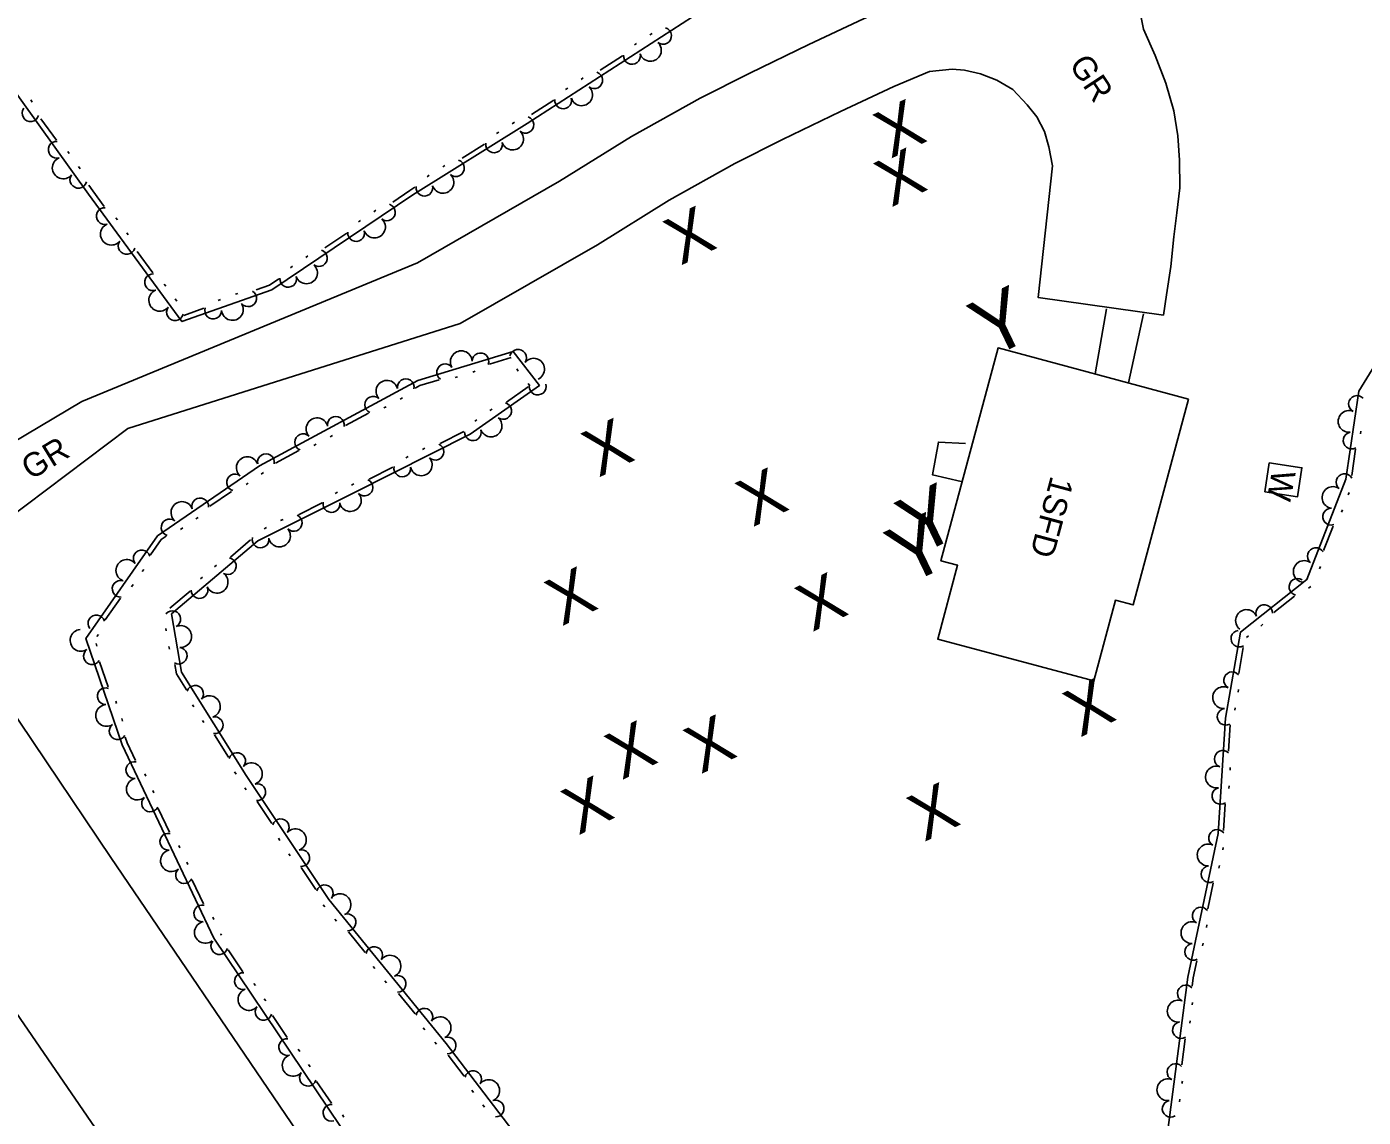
# Model space of a CAD drawing. Extents: x 2030130 to 2036320, y 723205 to 762423.
# Drawn here: x 2033389.9 to 2033597.2, y 761198.4 to 761367.6 of the extents above; entities that cross this region are included whole.
import ezdxf

# ---------------------------------------------------------------- set-up
doc = ezdxf.new("R2010")
doc.units = 0
for name, color, linetype in [('Draft_Station Labels Major', 7, 'Continuous'), ('Draft_Station Tics Major', 7, 'Continuous'), ('Exist Terrain Model Ground Surface', 7, 'Continuous'), ('Old_Level_23', 7, 'Continuous'), ('Old_Level_28', 7, 'Continuous')]:
    doc.layers.add(name, color=color, linetype=linetype)

msp = doc.modelspace()

# ---------------------------------------------------------------- linework, layer by layer
at = {"layer": 'Draft_Station Labels Major'}
for p, q in [((2033450.49, 761331), (2033398.43, 761309.47)), ((2033457.11, 761321.56), (2033405.58, 761305.29))]:
    msp.add_line(p, q, dxfattribs=at)
for points in [[(2033450.49, 761331), (2033472.55, 761343.63), (2033483.7, 761350.58), (2033494.36, 761356.54), (2033502.08, 761360.39), (2033511.2, 761364.83), (2033519.73, 761368.8), (2033525.39, 761371.23)], [(2033562.32, 761371.35), (2033563.15, 761367.2), (2033564.95, 761363.15), (2033566.59, 761358.86), (2033567.83, 761354.54), (2033568.47, 761350.65), (2033568.74, 761346.9), (2033568.77, 761342.61), (2033568.3, 761338.73), (2033567.84, 761335.02), (2033567.41, 761330.4), (2033566.71, 761326.01), (2033566.24, 761322.86), (2033546.8, 761325.6), (2033549.01, 761346.01), (2033548.45, 761348.99), (2033547.76, 761351.35), (2033546.62, 761353.61), (2033545.09, 761355.46), (2033542.86, 761357.87), (2033540.41, 761359.31), (2033537.84, 761360.29), (2033535.35, 761360.85), (2033533.46, 761361.02), (2033529.92, 761360.67)], [(2033457.11, 761321.56), (2033478.45, 761333.78), (2033489.54, 761340.69), (2033499.73, 761346.39), (2033507.16, 761350.09), (2033516.13, 761354.46), (2033524.42, 761358.32), (2033529.92, 761360.67)], [(2033712.22, 760786.66), (2033683.84, 760828.02), (2033655.87, 760868.99), (2033628.83, 760908.43), (2033600.16, 760950.82), (2033571.79, 760992.23), (2033543.75, 761033.03), (2033515.6, 761074.29), (2033487.47, 761115.18), (2033459.15, 761156.4), (2033430.9, 761197.59), (2033402.93, 761238.74), (2033380.71, 761271.71), (2033360.2, 761301.06), (2033346.96, 761320.77)], [(2033361.9, 761300.44), (2033372.02, 761296.58), (2033378.83, 761297.84), (2033398.43, 761309.47)], [(2033325.26, 761306.74), (2033353.27, 761265.49), (2033381.46, 761224.47), (2033409.65, 761183.47), (2033437.67, 761142.45), (2033465.74, 761101.32), (2033493.99, 761060.24), (2033522.13, 761019.11), (2033550.25, 760977.98), (2033578.36, 760936.85), (2033606.28, 760895.5), (2033634.33, 760854.29), (2033662.48, 760813.18), (2033690.27, 760771.87)], [(2033405.58, 761305.29), (2033386.64, 761290.99), (2033380.05, 761284.03), (2033381.74, 761273.53)]]:
    msp.add_lwpolyline(points, dxfattribs=at)
at = {"layer": 'Draft_Station Tics Major'}
for points in [[(2033496.38, 761371.21), (2033467.55, 761352.57), (2033449.79, 761341.52), (2033427.9, 761326.78), (2033413.97, 761321.85), (2033399.47, 761341.65), (2033376.06, 761374.31)], [(2033484.5, 761365), (2033484.16, 761364.78)], [(2033486.91, 761366.56), (2033486.57, 761366.33)], [(2033482.32, 761363.09), (2033478.87, 761360.87)], [(2033476.24, 761359.65), (2033475.89, 761359.43)], [(2033473.83, 761358.09), (2033473.48, 761357.87)], [(2033390.76, 761355.91), (2033390.52, 761356.24)], [(2033471.64, 761356.19), (2033468.2, 761353.96)], [(2033394.49, 761350), (2033392.1, 761353.33)], [(2033465.57, 761352.78), (2033465.22, 761352.56)], [(2033463.13, 761351.26), (2033462.78, 761351.05)], [(2033396.5, 761347.91), (2033396.26, 761348.24)], [(2033460.91, 761349.4), (2033457.43, 761347.23)], [(2033398.17, 761345.57), (2033397.93, 761345.91)], [(2033452.34, 761344.55), (2033451.99, 761344.33)], [(2033454.77, 761346.07), (2033454.42, 761345.85)], [(2033401.92, 761339.69), (2033400.14, 761342.13), (2033399.51, 761343)], [(2033450.11, 761342.69), (2033449.34, 761342.2), (2033446.67, 761340.41)], [(2033403.95, 761337.62), (2033403.7, 761337.95)], [(2033444.06, 761339.14), (2033443.72, 761338.91)], [(2033441.68, 761337.54), (2033441.34, 761337.31)], [(2033405.64, 761335.3), (2033405.4, 761335.63)], [(2033439.53, 761335.59), (2033436.12, 761333.3)], [(2033409.43, 761329.44), (2033407.01, 761332.75)], [(2033433.52, 761332.04), (2033433.17, 761331.81)], [(2033431.13, 761330.44), (2033430.79, 761330.21)], [(2033411.46, 761327.36), (2033411.22, 761327.69)], [(2033428.98, 761328.49), (2033427.53, 761327.52), (2033425.51, 761326.8)], [(2033413.16, 761325.05), (2033412.92, 761325.38)], [(2033422.66, 761326.23), (2033422.28, 761326.1)], [(2033417.39, 761323.93), (2033414.27, 761322.83)], [(2033419.96, 761325.28), (2033419.57, 761325.14)], [(2033604, 761323.17), (2033596.57, 761311.06), (2033594.52, 761297.4), (2033588.46, 761281.83), (2033578.2, 761273.7), (2033575.86, 761260.34), (2033574.71, 761242.44), (2033570.04, 761220.18), (2033566.67, 761194.48)], [(2033485.97, 761169.22), (2033454.96, 761209.86), (2033436.75, 761232.24), (2033423.94, 761251.45), (2033413.9, 761267.5), (2033412.33, 761276.52), (2033425.74, 761287.86), (2033440.52, 761295.23), (2033458.67, 761304.38), (2033469.44, 761311.97), (2033465.34, 761317.24), (2033450.59, 761312.7), (2033426, 761299.51), (2033410.19, 761288.65), (2033399.08, 761272.7), (2033404.72, 761256.21), (2033418.93, 761226.23), (2033495.84, 761111.88)], [(2033465.04, 761316.29), (2033461.7, 761315.27)], [(2033456.73, 761313.31), (2033456.34, 761313.18)], [(2033459.47, 761314.15), (2033459.08, 761314.03)], [(2033466.15, 761314.19), (2033465.9, 761314.51)], [(2033453.86, 761312.85), (2033450.9, 761311.94), (2033450.16, 761311.54)], [(2033464.33, 761309.38), (2033467.68, 761311.74)], [(2033467.92, 761311.92), (2033467.67, 761312.25)], [(2033448.18, 761310.02), (2033447.82, 761309.82)], [(2033442.93, 761307.66), (2033439.32, 761305.72)], [(2033445.66, 761308.66), (2033445.29, 761308.46)], [(2033461.75, 761308.06), (2033462.08, 761308.29)], [(2033454.02, 761302.95), (2033457.68, 761304.8)], [(2033459.4, 761306.4), (2033459.74, 761306.64)], [(2033596.88, 761304.85), (2033596.82, 761304.44)], [(2033434.81, 761302.84), (2033434.45, 761302.65)], [(2033437.34, 761304.2), (2033436.98, 761304)], [(2033432.09, 761301.84), (2033428.48, 761299.9)], [(2033448.71, 761300.73), (2033449.07, 761300.92)], [(2033451.27, 761302.03), (2033451.64, 761302.21)], [(2033596.05, 761302.07), (2033595.44, 761298.01)], [(2033426.62, 761298.44), (2033426.28, 761298.21)], [(2033443.03, 761297.41), (2033446.69, 761299.26)], [(2033424.26, 761296.82), (2033423.92, 761296.58)], [(2033440.28, 761296.49), (2033440.65, 761296.67)], [(2033421.66, 761295.53), (2033418.28, 761293.21)], [(2033437.72, 761295.21), (2033438.09, 761295.39)], [(2033595.04, 761295.35), (2033594.9, 761294.97)], [(2033432.03, 761291.91), (2033435.7, 761293.74)], [(2033594, 761292.68), (2033593.85, 761292.3)], [(2033416.48, 761291.48), (2033416.14, 761291.24)], [(2033429.28, 761290.99), (2033429.65, 761291.18)], [(2033592.58, 761290.15), (2033591.09, 761286.33)], [(2033411.51, 761288.57), (2033410.77, 761288.06), (2033409.11, 761285.67)], [(2033414.11, 761289.85), (2033413.77, 761289.62)], [(2033426.71, 761289.71), (2033427.08, 761289.9)], [(2033421.5, 761285.34), (2033424.63, 761287.99)], [(2033419.04, 761283.8), (2033419.35, 761284.07)], [(2033590.58, 761283.89), (2033590.43, 761283.5)], [(2033408.04, 761283.42), (2033407.81, 761283.08)], [(2033416.85, 761281.95), (2033417.16, 761282.22)], [(2033406.41, 761281.07), (2033406.17, 761280.73)], [(2033412.1, 761277.4), (2033415.23, 761280.05)], [(2033589.08, 761280.75), (2033588.76, 761280.5)], [(2033404.43, 761278.94), (2033402.08, 761275.58)], [(2033586.57, 761279.29), (2033583.36, 761276.75)], [(2033411.54, 761273.87), (2033411.47, 761274.27)], [(2033581.68, 761274.9), (2033581.36, 761274.64)], [(2033400.66, 761271.91), (2033400.79, 761271.52)], [(2033401.01, 761273.32), (2033400.78, 761272.99)], [(2033412.03, 761271.04), (2033411.96, 761271.45)], [(2033579.43, 761273.12), (2033579.11, 761272.86)], [(2033578.61, 761271.33), (2033577.91, 761267.29)], [(2033401.19, 761269.06), (2033402.52, 761265.18)], [(2033414.66, 761264.73), (2033413.12, 761267.2), (2033412.86, 761268.69)], [(2033577.89, 761264.8), (2033577.81, 761264.39)], [(2033403.7, 761262.99), (2033403.84, 761262.6)], [(2033415.84, 761262.08), (2033415.62, 761262.43)], [(2033577.39, 761261.97), (2033577.32, 761261.56)], [(2033404.63, 761260.27), (2033404.76, 761259.88)], [(2033417.36, 761259.65), (2033417.14, 761260)], [(2033576.61, 761259.29), (2033576.35, 761255.2)], [(2033405.17, 761257.42), (2033405.48, 761256.52), (2033406.79, 761253.76)], [(2033421.19, 761254.3), (2033419.01, 761257.78)], [(2033408.21, 761251.71), (2033408.39, 761251.34)], [(2033422.36, 761251.65), (2033422.14, 761252)], [(2033576.6, 761252.71), (2033576.58, 761252.3)], [(2033409.44, 761249.11), (2033409.62, 761248.74)], [(2033423.95, 761249.21), (2033423.72, 761249.55)], [(2033576.42, 761249.85), (2033576.39, 761249.44)], [(2033427.93, 761243.98), (2033425.65, 761247.4)], [(2033575.83, 761247.01), (2033575.57, 761242.92)], [(2033410.3, 761246.34), (2033412.06, 761242.64)], [(2033413.49, 761240.59), (2033413.66, 761240.22)], [(2033429.18, 761241.37), (2033428.96, 761241.71)], [(2033430.78, 761238.98), (2033430.55, 761239.32)], [(2033575.52, 761240.3), (2033575.44, 761239.9)], [(2033414.72, 761238), (2033414.89, 761237.63)], [(2033434.76, 761233.75), (2033432.48, 761237.16)], [(2033574.93, 761237.49), (2033574.85, 761237.09)], [(2033415.58, 761235.23), (2033417.33, 761231.52)], [(2033573.94, 761234.76), (2033573.1, 761230.75)], [(2033436.12, 761231.07), (2033435.86, 761231.39)], [(2033418.76, 761229.48), (2033418.93, 761229.1)], [(2033437.93, 761228.84), (2033437.67, 761229.16)], [(2033572.99, 761228.26), (2033572.91, 761227.85)], [(2033419.99, 761226.88), (2033420, 761226.85), (2033420.11, 761226.69)], [(2033442.39, 761224.01), (2033439.8, 761227.19)], [(2033421.14, 761224.42), (2033423.43, 761221.02)], [(2033572.4, 761225.45), (2033572.32, 761225.05)], [(2033443.88, 761221.53), (2033443.63, 761221.84)], [(2033571.41, 761222.72), (2033570.85, 761220.04), (2033570.68, 761218.75)], [(2033445.7, 761219.3), (2033445.44, 761219.62)], [(2033425.14, 761219.21), (2033425.37, 761218.86)], [(2033450.15, 761214.47), (2033447.57, 761217.65)], [(2033426.74, 761216.82), (2033426.97, 761216.48)], [(2033570.77, 761216.26), (2033570.71, 761215.85)], [(2033428.01, 761214.21), (2033430.3, 761210.81)], [(2033570.39, 761213.41), (2033570.34, 761213.01)], [(2033451.65, 761211.98), (2033451.39, 761212.3)], [(2033453.46, 761209.76), (2033453.2, 761210.08)], [(2033569.61, 761210.62), (2033569.08, 761206.56)], [(2033432.01, 761209), (2033432.24, 761208.66)], [(2033457.76, 761204.83), (2033455.28, 761208.09)], [(2033433.61, 761206.61), (2033433.84, 761206.27)], [(2033434.87, 761204), (2033437.16, 761200.6)], [(2033569.17, 761204.06), (2033569.11, 761203.66)], [(2033459.18, 761202.3), (2033458.93, 761202.63)], [(2033568.79, 761201.22), (2033568.74, 761200.81)], [(2033460.92, 761200.02), (2033460.67, 761200.35)], [(2033438.88, 761198.79), (2033439.1, 761198.45)]]:
    msp.add_lwpolyline(points, dxfattribs=at)
for centre, radius, start, end in [((2033488.61, 761366.19), 1.3, 231.3409, 72.1375), ((2033486.65, 761363.94), 1.69, 198.8697, 46.9422), ((2033483.79, 761363.07), 1.3, 173.6745, 14.471), ((2033477.94, 761359.29), 1.3, 231.3409, 72.1375), ((2033473.12, 761356.17), 1.3, 173.6745, 14.471), ((2033475.98, 761357.04), 1.69, 198.8697, 46.9422), ((2033390.48, 761354.19), 1.3, 144.067, 344.8635), ((2033467.26, 761352.38), 1.3, 230.3096, 71.1062), ((2033465.26, 761350.17), 1.69, 197.8384, 45.9109), ((2033394.54, 761348.52), 1.3, 86.4005, 287.1971), ((2033462.39, 761349.35), 1.3, 172.6432, 13.4397), ((2033395.55, 761345.71), 1.69, 111.5958, 319.6683), ((2033456.47, 761345.67), 1.3, 230.3096, 71.1062), ((2033397.89, 761343.86), 1.3, 144.067, 344.8635), ((2033454.46, 761343.46), 1.69, 197.8384, 45.9109), ((2033451.59, 761342.64), 1.3, 172.6432, 13.4397), ((2033445.77, 761338.81), 1.3, 232.3943, 73.1908), ((2033401.99, 761338.22), 1.3, 86.9948, 287.7914), ((2033443.84, 761336.53), 1.69, 199.9231, 47.9956), ((2033403.02, 761335.42), 1.69, 112.1901, 320.2626), ((2033441, 761335.6), 1.3, 174.7278, 15.5244), ((2033405.38, 761333.58), 1.3, 144.6613, 345.4579), ((2033435.22, 761331.71), 1.3, 232.3943, 73.1908), ((2033433.3, 761329.42), 1.69, 199.9231, 47.9956), ((2033409.5, 761327.96), 1.3, 86.9948, 287.7914), ((2033430.46, 761328.5), 1.3, 174.7278, 15.5244), ((2033410.53, 761325.16), 1.69, 112.1901, 320.2626), ((2033424.24, 761325.48), 1.3, 217.8988, 58.6954), ((2033412.89, 761323.33), 1.3, 144.6613, 345.4579), ((2033418.82, 761323.57), 1.3, 160.2323, 1.0289), ((2033421.8, 761323.75), 1.69, 185.4276, 33.5001), ((2033457.3, 761315.63), 1.69, 3.0862, 211.1587), ((2033466.12, 761316.24), 1.3, 326.3143, 167.1108), ((2033454.8, 761314), 1.3, 35.5574, 236.3539), ((2033460.28, 761315.69), 1.3, 337.8909, 178.6875), ((2033468.53, 761314.48), 1.69, 293.8431, 141.9156), ((2033448.69, 761311.68), 1.3, 348.9894, 189.786), ((2033445.77, 761311.05), 1.69, 14.1847, 222.2571), ((2033469.16, 761311.78), 1.3, 175.9732, 16.7698), ((2033443.63, 761308.97), 1.3, 46.6559, 247.4524), ((2033463.8, 761308), 1.3, 233.6397, 74.4363), ((2033596.27, 761309.09), 1.3, 42.2441, 243.0407), ((2033434.93, 761305.23), 1.69, 14.1847, 222.2571), ((2033437.84, 761305.86), 1.3, 348.9894, 189.786), ((2033461.93, 761305.67), 1.69, 201.1685, 49.241), ((2033595.04, 761306.37), 1.69, 67.4394, 275.5119), ((2033459.11, 761304.69), 1.3, 175.9732, 16.7698), ((2033595.42, 761303.41), 1.3, 99.9106, 300.7072), ((2033432.79, 761303.15), 1.3, 46.6559, 247.4524), ((2033453.29, 761301.67), 1.3, 225.1934, 65.9899), ((2033424.11, 761299.2), 1.69, 20.4291, 228.5016), ((2033427, 761300.04), 1.3, 348.9894, 189.786), ((2033451.09, 761299.64), 1.69, 192.7222, 40.7947), ((2033448.16, 761299.08), 1.3, 167.5269, 8.3235), ((2033422.21, 761296.9), 1.3, 52.9003, 253.6969), ((2033442.3, 761296.13), 1.3, 225.1934, 65.9899), ((2033594.34, 761296.95), 1.3, 29.5052, 230.3017), ((2033416.8, 761293.19), 1.3, 355.2339, 196.0304), ((2033440.1, 761294.1), 1.69, 192.4766, 40.5491), ((2033592.54, 761294.57), 1.69, 54.7004, 262.7729), ((2033413.97, 761292.24), 1.69, 20.4291, 228.5016), ((2033437.17, 761293.56), 1.3, 167.2814, 8.0779), ((2033592.26, 761291.6), 1.3, 87.1716, 287.9682), ((2033412.06, 761289.94), 1.3, 52.9003, 253.6969), ((2033431.3, 761290.63), 1.3, 224.9478, 65.7444), ((2033426.16, 761288.06), 1.3, 167.2814, 8.0779), ((2033429.1, 761288.61), 1.69, 192.4766, 40.5491), ((2033407.74, 761285.13), 1.3, 15.9241, 216.7206), ((2033589.88, 761285.48), 1.3, 29.5052, 230.3017), ((2033405.42, 761283.25), 1.69, 41.1193, 249.1918), ((2033421.09, 761283.92), 1.3, 238.6283, 79.4248), ((2033588.08, 761283.1), 1.69, 54.7004, 262.7729), ((2033419.42, 761281.44), 1.69, 206.1571, 54.2296), ((2033587.03, 761280.7), 1.3, 56.8106, 257.6072), ((2033404.46, 761280.42), 1.3, 73.5905, 274.3871), ((2033416.7, 761280.22), 1.3, 180.9618, 21.7584), ((2033581.88, 761276.63), 1.3, 359.1442, 199.9407), ((2033400.71, 761275.04), 1.3, 15.9241, 216.7206), ((2033412.47, 761275.7), 1.3, 298.3403, 139.1369), ((2033579.13, 761275.49), 1.69, 24.3394, 232.4119), ((2033398.32, 761272.41), 1.69, 94.8243, 302.8968), ((2033413.77, 761273.01), 1.69, 265.8691, 113.9416), ((2033578.02, 761272.68), 1.3, 98.4998, 299.2964), ((2033400.02, 761269.96), 1.3, 127.2955, 328.0921), ((2033413.46, 761270.04), 1.3, 240.6739, 81.4704), ((2033576.89, 761266.22), 1.3, 40.8334, 241.6299), ((2033416.01, 761264.12), 1.3, 320.4498, 161.2464), ((2033575.58, 761263.53), 1.69, 66.0286, 274.1011), ((2033402.14, 761263.75), 1.3, 69.629, 270.4256), ((2033418.23, 761262.13), 1.69, 287.9786, 136.0511), ((2033402.29, 761260.77), 1.69, 94.8243, 302.8968), ((2033575.89, 761260.56), 1.3, 98.4998, 299.2964), ((2033404, 761258.32), 1.3, 127.2955, 328.0921), ((2033419.05, 761259.26), 1.3, 262.7833, 103.5799), ((2033422.53, 761253.69), 1.3, 320.4498, 161.2464), ((2033575.45, 761254.02), 1.3, 47.1189, 247.9155), ((2033406.58, 761252.29), 1.3, 76.1388, 276.9354), ((2033424.74, 761251.72), 1.69, 289.6787, 137.7512), ((2033574.45, 761251.21), 1.69, 72.3142, 280.3867), ((2033407.06, 761249.35), 1.69, 101.3341, 309.4066), ((2033425.65, 761248.87), 1.3, 264.4834, 105.28), ((2033575.09, 761248.29), 1.3, 104.7854, 305.582), ((2033409.04, 761247.11), 1.3, 133.8053, 334.6019), ((2033429.3, 761243.42), 1.3, 322.1499, 162.9464), ((2033411.85, 761241.18), 1.3, 76.1388, 276.9354), ((2033431.57, 761241.48), 1.69, 289.6787, 137.7512), ((2033574.57, 761241.75), 1.3, 38.9145, 239.7111), ((2033573.18, 761239.11), 1.69, 64.1098, 272.1823), ((2033412.34, 761238.23), 1.69, 101.3341, 309.4066), ((2033432.48, 761238.64), 1.3, 264.4834, 105.28), ((2033414.31, 761235.99), 1.3, 133.8053, 334.6019), ((2033573.39, 761236.14), 1.3, 96.581, 297.3775), ((2033436.12, 761233.18), 1.3, 322.1499, 162.9464), ((2033438.49, 761231.41), 1.69, 295.0936, 143.1661), ((2033417.12, 761230.06), 1.3, 76.1388, 276.9354), ((2033439.66, 761228.67), 1.3, 269.8984, 110.6949), ((2033572.04, 761229.71), 1.3, 38.9145, 239.7111), ((2033417.61, 761227.12), 1.69, 101.3341, 309.4066), ((2033570.65, 761227.07), 1.69, 64.1098, 272.1823), ((2033419.77, 761224.98), 1.3, 142.3582, 343.1547), ((2033443.8, 761223.58), 1.3, 327.5648, 168.3614), ((2033570.86, 761224.1), 1.3, 96.581, 297.3775), ((2033446.25, 761221.87), 1.69, 295.0936, 143.1661), ((2033423.44, 761219.54), 1.3, 84.6917, 285.4883), ((2033447.43, 761219.12), 1.3, 269.8984, 110.6949), ((2033424.36, 761216.7), 1.69, 109.887, 317.9594), ((2033569.71, 761217.64), 1.3, 43.2944, 244.091), ((2033426.64, 761214.78), 1.3, 142.3582, 343.1547), ((2033568.52, 761214.9), 1.69, 68.4897, 276.5622), ((2033451.57, 761214.03), 1.3, 327.5648, 168.3614), ((2033454.02, 761212.32), 1.69, 295.0936, 143.1661), ((2033568.96, 761211.95), 1.3, 100.9609, 301.7574), ((2033430.3, 761209.33), 1.3, 84.6917, 285.4883), ((2033455.18, 761209.57), 1.3, 268.1117, 108.9082), ((2033431.22, 761206.49), 1.69, 109.887, 317.9594), ((2033433.51, 761204.57), 1.3, 142.3582, 343.1547), ((2033459.16, 761204.35), 1.3, 325.7781, 166.5747), ((2033568.11, 761205.44), 1.3, 43.2944, 244.091), ((2033461.56, 761202.57), 1.69, 293.307, 141.3794), ((2033566.92, 761202.7), 1.69, 68.4897, 276.5622), ((2033462.64, 761199.79), 1.3, 268.1117, 108.9082), ((2033567.36, 761199.75), 1.3, 100.9609, 301.7574), ((2033437.17, 761199.12), 1.3, 84.6917, 285.4883)]:
    msp.add_arc(centre, radius, start, end, dxfattribs=at)
at = {"layer": 'Exist Terrain Model Ground Surface'}
for points in [[(2033557.4, 761323.84), (2033555.63, 761313.74)], [(2033560.84, 761312.34), (2033563.13, 761323.06)], [(2033535.52, 761302.97), (2033531.33, 761303.17), (2033530.42, 761298.08), (2033534.85, 761297.08)]]:
    msp.add_lwpolyline(points, dxfattribs=at)
for points in [[(2033570.12, 761309.85), (2033561.54, 761277.91), (2033558.8, 761278.64), (2033555.44, 761266.11), (2033531.22, 761272.61), (2033534.3, 761284.07), (2033531.71, 761284.76), (2033540.58, 761317.78)], [(2033581.97, 761295.43), (2033587.03, 761294.66), (2033587.72, 761299.18), (2033582.66, 761299.95)]]:
    msp.add_lwpolyline(points, close=True, dxfattribs=at)

# ---------------------------------------------------------------- texts
at = {"layer": 'Draft_Station Tics Major'}
for s, height, rotation, p in [('X', 7.38, 25.7434, (2033523.89, 761347.09)), ('X', 7.38, 25.7434, (2033523.99, 761339.56)), ('X', 7.38, 25.7434, (2033491.31, 761330.52)), ('Y', 9.02, 25.7438, (2033539.2, 761316.06)), ('X', 7.38, 25.7434, (2033478.58, 761297.63)), ('X', 7.38, 25.7434, (2033502.5, 761289.94)), ('Y', 9.02, 25.7438, (2033527.99, 761285.45)), ('Y', 9.02, 25.7438, (2033526.33, 761280.86)), ('X', 7.38, 25.7434, (2033472.88, 761274.57)), ('X', 7.38, 25.7434, (2033511.73, 761273.68)), ('X', 7.38, 25.7434, (2033553.28, 761257.33)), ('X', 7.38, 25.7434, (2033482.18, 761250.71)), ('X', 7.38, 25.7434, (2033494.44, 761251.63)), ('X', 7.38, 25.7434, (2033475.44, 761242.14)), ('X', 7.38, 25.7434, (2033529.1, 761241.11))]:
    msp.add_text(s, height=height, rotation=rotation, dxfattribs=at).set_placement(p)
at = {"layer": 'Old_Level_23'}
for rotation, p in [(303.5008, (2033551.5, 761361.74)), (31.3644, (2033390.52, 761297.2))]:
    msp.add_text('GR', height=3.691, rotation=rotation, dxfattribs=at).set_placement(p)
at = {"layer": 'Old_Level_28'}
for s, height, rotation, p in [('1SFD', 3.691, 254.9591, (2033548.79, 761298.05)), ('W', 3.69, 259.5742, (2033583.13, 761299.06))]:
    msp.add_text(s, height=height, rotation=rotation, dxfattribs=at).set_placement(p)

doc.saveas('drawing.dxf')
